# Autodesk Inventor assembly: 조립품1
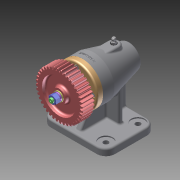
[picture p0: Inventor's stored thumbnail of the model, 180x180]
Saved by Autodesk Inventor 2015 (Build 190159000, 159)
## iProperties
Created: 2024-12
Part Number: 조립품1
Document SubType Name: Assembly
Designer: 102566
Author: 102566
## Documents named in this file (15)
- C:\Users\102566\Desktop\741204V1008\답안 조립품.iam
- C:\Users\102566\Desktop\741204V1008\본체.ipt
- C:\Users\102566\Desktop\741204V1008\앵귤러 볼 베어링 7003A.ipt
- C:\Users\102566\Desktop\741204V1008\앵귤러 볼 제어링 7204A.ipt
- C:\Users\102566\Desktop\741204V1008\오일 실 20 32 8.ipt
- C:\Users\102566\Desktop\741204V1008\축.ipt
- C:\Users\102566\Desktop\741204V1008\커버.ipt
- C:\Users\102566\Desktop\741204V1008\육각 소켓 머리 볼트 M4x10.ipt
- C:\Users\102566\Desktop\741204V1008\스퍼기어.ipt
- C:\Users\102566\Desktop\741204V1008\스프링 와셔 M8.ipt
- C:\Users\102566\Desktop\741204V1008\육각 너트 M8.ipt
- C:\Users\102566\Desktop\741204V1008\평와셔 M8.ipt
- C:\Users\102566\Desktop\741204V1008\평행 키 4x4x14.ipt
- C:\Users\102566\Desktop\741204V1008\그리스 니플 M6x0.75.ipt
- C:\Users\102566\Desktop\741204V1008\실링.ipt
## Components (1 placed, 1 different names)
1. 그리스 니플 M6x0.75:1
